Omron CX-Programmer project 新規ﾌﾟﾛｼﾞｪｸﾄ (CX-Programmer 9.75)

# PLC 新規PLC1: CJ2M CPU11

## Program 新規ﾌﾟﾛｸﾞﾗﾑ1 (cyclic task 0)

### Section ｾｸｼｮﾝ1

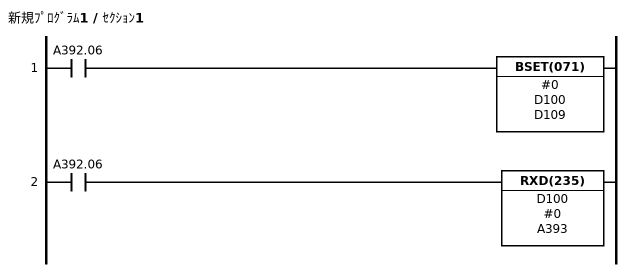
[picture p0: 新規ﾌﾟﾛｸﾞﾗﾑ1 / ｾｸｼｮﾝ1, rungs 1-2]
; rung 1
LD A392.06
BSET(071) #0 D100 D109
; rung 2
LD A392.06
RXD(235) D100 #0 A393

### Section END
; rung 0
END(001)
